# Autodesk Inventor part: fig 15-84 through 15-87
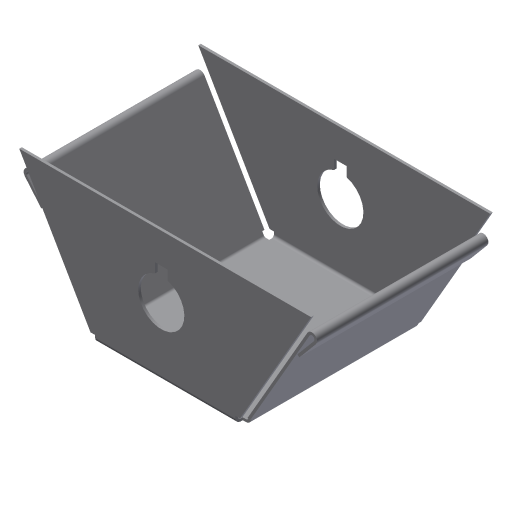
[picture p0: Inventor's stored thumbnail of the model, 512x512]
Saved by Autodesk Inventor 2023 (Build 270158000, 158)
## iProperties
Created: 2002-04
Part Number: fig 15-84 through 15-87
Document SubType Name: Sheet Metal
Density: 1 g/cm^3
Sheet Metal Rule: Default
Material: Generic
Appearance: Default
Control State: 0
Master: False
Checked Out: False
Shininess: 50.0
Angle Display Precision: 2
Document Length Units: 11269
Document Angle Units: 11279
Document Time Units: 11290
Document Mass Units: 11283
Document Length Units Precision: 3
Document Angle Units Precision: 2
Density: 0.0
Volumn: 0.0
Area: 0.0
PropertySet Name: Model Information
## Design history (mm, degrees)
node "Face1"
  sketch "Sketch1"
    geometry: L1 (-24.824, 17.882)-(5.529, 17.882); L2 (5.529, 17.882)-(5.529, -17.529); L3 (5.529, -17.529)-(-24.824, -17.529); L4 (-24.824, -17.529)-(-24.824, 17.882)
    constraints: 8 end point, 2 parallel, 1 horizontal, 1 perpendicular
node "Flange2"
node "Flange3"
node "Flange4"
node "Flange5"
feature "Corner1" dims "d45" = 0.5 (= Thickness), "d46" = 0, "d81" = 2 (= CornerReliefSize), "d85" = 0.5 (= Thickness), "TransitionRadius" = 0.5 (= BendRadius)
feature "Corner2" dims "d47" = 0.5 (= Thickness), "d48" = 0, "d82" = 2 (= CornerReliefSize), "d85" = 0.5 (= Thickness), "TransitionRadius" = 0.5 (= BendRadius)
feature "Corner3" dims "d49" = 0.5 (= Thickness), "d50" = 0, "d83" = 2 (= CornerReliefSize), "d85" = 0.5 (= Thickness), "TransitionRadius" = 0.5 (= BendRadius)
feature "Corner4" dims "d51" = 0.5 (= Thickness), "d52" = 0, "d84" = 2 (= CornerReliefSize), "d85" = 0.5 (= Thickness), "TransitionRadius" = 0.5 (= BendRadius)
feature "Hem1" dims "d53" = 0.5 (= BendRadius), "d54" = 190 deg, "d55" = 0.5 (= BendRadius), "d56" = 0.5 (= d55), "d75" = 0.5 (= BendReliefWidth), "d76" = 0.25 (= BendReliefDepth), "d77" = 1 (= MinimumRemnant), "d85" = 0.5 (= Thickness), "SeamGap" = 0.01, "MinimumRemnant" = 1 (= 2 x Thickness), "BendReliefWidth" = 0.5 (= Thickness)
feature "Hem2" dims "d57" = 0.5 (= BendRadius), "d58" = 190 deg, "d59" = 0.5 (= BendRadius), "d60" = 0.5 (= d59), "d78" = 0.5 (= BendReliefWidth), "d79" = 0.25 (= BendReliefDepth), "d80" = 1 (= MinimumRemnant), "d85" = 0.5 (= Thickness), "SeamGap" = 0.01, "MinimumRemnant" = 1 (= 2 x Thickness), "BendReliefWidth" = 0.5 (= Thickness)
sketch "Sketch12"
  geometry: L1 (28.924, -7.829)-(28.924, -5.94); L2 (28.924, -5.94)-(26.464, -5.94); L3 (26.464, -5.94)-(26.464, -7.829); A1 r 4.497 centre (27.694, -12.155) between (26.464, -7.829) and (28.924, -7.829)
  constraints: 6 end point, 2 point on circle, 1 centre point, 1 parallel
cut "Cut1" sketch "Sketch12" dims "d61" = 0.5 (= Thickness), "d62" = 0
body "Solid1"
face "Plate1" dims "d85" = 0.5 (= Thickness)
sketch "Sketch6"
  geometry: L1 (30.412, 0)-(5, 0); L2 (5, 0)-(5, 25); L3 (5, 25)-(30.412, 25); L4 (30.412, 25)-(30.412, 0)
  constraints: 8 end point
face "Plate7" dims "d21" = 5, "d22" = 5, "d24" = 25, "d25" = 60 deg, "d26" = 0.5 (= BendRadius), "d85" = 0.5 (= Thickness), "MinimumRemnant" = 1 (= 2 x Thickness), "BendReliefWidth" = 0.5 (= Thickness)
bend "Bend6" dims "d23" = 0.5 (= BendRadius), "d24" = 25, "d25" = 60 deg, "d26" = 0.5 (= BendRadius), "d63" = 0.5 (= BendReliefWidth), "d64" = 0.25 (= BendReliefDepth), "d65" = 1 (= MinimumRemnant), "d85" = 0.5 (= Thickness), "SeamGap" = 0.01, "MinimumRemnant" = 1 (= 2 x Thickness), "BendReliefWidth" = 0.5 (= Thickness)
sketch "Sketch7"
  geometry: L1 (25.353, 0)-(5, 0); L2 (5, 0)-(5, 25); L3 (5, 25)-(25.353, 25); L4 (25.353, 25)-(25.353, 0)
  constraints: 8 end point
face "Plate8" dims "d27" = 5, "d28" = 5, "d30" = 25, "d31" = 90 deg, "d32" = 0.5 (= BendRadius), "d85" = 0.5 (= Thickness), "MinimumRemnant" = 1 (= 2 x Thickness), "BendReliefWidth" = 0.5 (= Thickness)
bend "Bend7" dims "d29" = 0.5 (= BendRadius), "d30" = 25, "d31" = 90 deg, "d32" = 0.5 (= BendRadius), "d66" = 0.5 (= BendReliefWidth), "d67" = 0.25 (= BendReliefDepth), "d68" = 1 (= MinimumRemnant), "d85" = 0.5 (= Thickness), "SeamGap" = 0.01, "MinimumRemnant" = 1 (= 2 x Thickness), "BendReliefWidth" = 0.5 (= Thickness)
sketch "Sketch8"
  geometry: L1 (5, 0)-(30.412, 0); L2 (30.412, 0)-(30.412, 25); L3 (30.412, 25)-(5, 25); L4 (5, 25)-(5, 0)
  constraints: 8 end point
face "Plate9" dims "d33" = 5, "d34" = 5, "d36" = 25, "d37" = 60 deg, "d38" = 0.5 (= BendRadius), "d85" = 0.5 (= Thickness), "MinimumRemnant" = 1 (= 2 x Thickness), "BendReliefWidth" = 0.5 (= Thickness)
bend "Bend8" dims "d35" = 0.5 (= BendRadius), "d36" = 25, "d37" = 60 deg, "d38" = 0.5 (= BendRadius), "d69" = 0.5 (= BendReliefWidth), "d70" = 0.25 (= BendReliefDepth), "d71" = 1 (= MinimumRemnant), "d85" = 0.5 (= Thickness), "SeamGap" = 0.01, "MinimumRemnant" = 1 (= 2 x Thickness), "BendReliefWidth" = 0.5 (= Thickness)
sketch "Sketch9"
  geometry: L1 (5, 0)-(25.353, 0); L2 (25.353, 0)-(25.353, 25); L3 (25.353, 25)-(5, 25); L4 (5, 25)-(5, 0)
  constraints: 8 end point
face "Plate10" dims "d39" = 5, "d40" = 5, "d42" = 25, "d43" = 90 deg, "d44" = 0.5 (= BendRadius), "d85" = 0.5 (= Thickness), "MinimumRemnant" = 1 (= 2 x Thickness), "BendReliefWidth" = 0.5 (= Thickness)
bend "Bend9" dims "d41" = 0.5 (= BendRadius), "d42" = 25, "d43" = 90 deg, "d44" = 0.5 (= BendRadius), "d72" = 0.5 (= BendReliefWidth), "d73" = 0.25 (= BendReliefDepth), "d74" = 1 (= MinimumRemnant), "d85" = 0.5 (= Thickness), "SeamGap" = 0.01, "MinimumRemnant" = 1 (= 2 x Thickness), "BendReliefWidth" = 0.5 (= Thickness)
sketch "Sketch10"
  geometry: L1 (0.433, 0.25)-(0, 0); L2 (-0.816, -0.571)-(2.395, -4.398); L3 (2.395, -4.398)-(2.012, -4.719); L4 (2.012, -4.719)-(-1.199, -0.893); A1 r 0.5 centre (-0.433, -0.25) between (0, 0) and (-0.816, -0.571); A2 r 1 centre (-0.433, -0.25) between (0.433, 0.25) and (-1.199, -0.893)
  constraints: 8 end point, 4 point on circle
sketch "Sketch11"
  geometry: L1 (0.433, 0.25)-(0, 0); L2 (-0.816, -0.571)-(2.395, -4.398); L3 (2.395, -4.398)-(2.012, -4.719); L4 (2.012, -4.719)-(-1.199, -0.893); A1 r 0.5 centre (-0.433, -0.25) between (0, 0) and (-0.816, -0.571); A2 r 1 centre (-0.433, -0.25) between (0.433, 0.25) and (-1.199, -0.893)
  constraints: 8 end point, 4 point on circle
node "FlatPattern"
feature "FlatPatternExtrusion2" dims "d0" = 0.5 (derived)
other parameters: "Thickness" = 0.5, "BendRadius" = 0.5 (= Thickness), "BendReliefDepth" = 0.25 (= 0.5 x Thickness), "CornerReliefSize" = 2 (= 4 x Thickness), "d0" = 0.5 (= BendRadius), "d4" = 0.5 (= BendRadius), "JacobiRadiusSize" = 0.5 (= Thickness), "GapSize" = 0.5 (= Thickness)
